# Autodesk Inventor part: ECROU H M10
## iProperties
Created: 2004-11
Part Number: ECROU H M10
Document SubType Name: Modeling
Designer: Bruno
Manufacturer: Standard
Standards Organization: Custom
Author: Bruno
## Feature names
1. Base1
